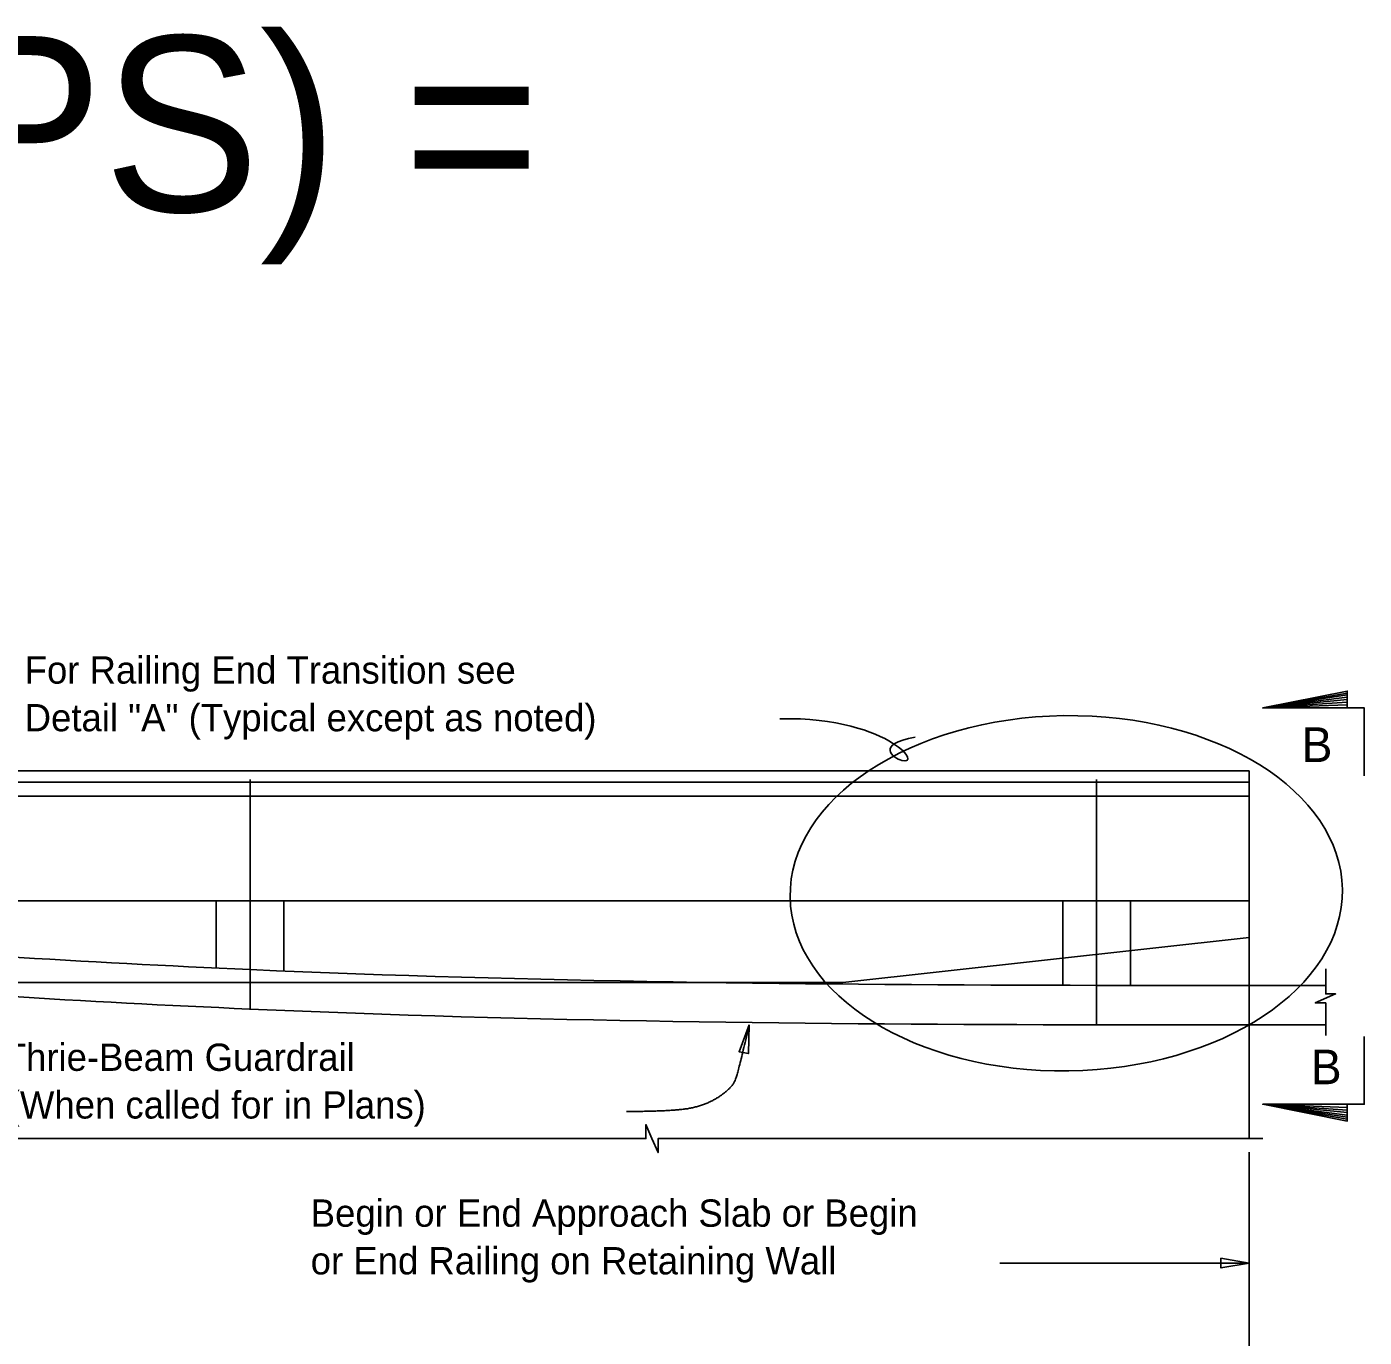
# Model space of a CAD drawing. Extents: x 130583.6 to 130653, y 88618.2 to 88652.9.
# Drawn here: x 130614.42 to 130624.29, y 88643.03 to 88652.71 of the extents above; entities that cross this region are included whole.
import ezdxf

# ---------------------------------------------------------------- set-up
doc = ezdxf.new("R2010")
doc.units = 0
for name, color, linetype in [('Dimension', 7, 'Continuous'), ('Miscellaneous', 7, 'Continuous'), ('TextStructures', 7, 'Continuous'), ('TrafBarrierConc', 7, 'Continuous')]:
    doc.layers.add(name, color=color, linetype=linetype)

msp = doc.modelspace()

# ---------------------------------------------------------------- linework, layer by layer
at = {"layer": 'Dimension'}
for p, q in [((130623.5402, 88647.6781), (130624.1652, 88647.7881)), ((130624.1652, 88647.7748), (130623.5402, 88647.6781)), ((130623.5402, 88647.6781), (130624.1652, 88647.7581)), ((130624.1652, 88647.7398), (130623.5402, 88647.6781)), ((130623.5402, 88647.6781), (130624.1652, 88647.7215)), ((130624.1652, 88647.7015), (130623.5402, 88647.6781)), ((130616.0642, 88647.1509), (130616.0642, 88645.4549)), ((130622.3142, 88647.1509), (130622.3142, 88645.3384)), ((130624.1652, 88644.7292), (130623.5402, 88644.7525)), ((130623.5402, 88644.7525), (130624.1652, 88644.7092)), ((130624.1652, 88644.6909), (130623.5402, 88644.7525)), ((130623.5402, 88644.7525), (130624.1652, 88644.6725)), ((130624.1652, 88644.6559), (130623.5402, 88644.7525)), ((130623.5402, 88644.7525), (130624.1652, 88644.6425)), ((130623.4397, 88638.1338), (130623.4397, 88644.3981)), ((130621.5998, 88643.5794), (130623.4397, 88643.5794))]:
    msp.add_line(p, q, dxfattribs=at)
for points in [[(130624.2902, 88647.1781), (130624.2902, 88647.6781), (130623.5402, 88647.6781), (130624.1652, 88647.8031), (130624.1652, 88647.6781)], [(130624.006, 88645.2589), (130624.006, 88645.5001), (130623.9285, 88645.5001), (130624.0785, 88645.5663), (130624.006, 88645.5663), (130624.006, 88645.7521)], [(130624.2902, 88645.2525), (130624.2902, 88644.7525), (130623.5402, 88644.7525), (130624.1652, 88644.6275), (130624.1652, 88644.7525)], [(130614.2317, 88644.4989), (130618.986, 88644.4989), (130618.986, 88644.6022), (130619.031, 88644.4989), (130619.076, 88644.3956), (130619.076, 88644.4989), (130623.5405, 88644.4989)]]:
    msp.add_lwpolyline(points, dxfattribs=at)
for points in [[(130619.7487, 88645.3379), (130619.6743, 88645.1402), (130619.7436, 88645.1268)], [(130623.4397, 88643.5794), (130623.2315, 88643.6147), (130623.2315, 88643.5441)]]:
    msp.add_lwpolyline(points, close=True, dxfattribs=at)
msp.add_ellipse((130622.0902, 88646.3101), major_axis=(2.0389, 0.0288), ratio=0.643163, dxfattribs=at)
for points, degree in [([(130620.9753, 88647.4629), (130620.6779, 88647.4097), (130620.9434, 88647.2079), (130620.9434, 88647.3991), (130620.3975, 88647.6078), (130619.9761, 88647.5987)], 3), ([(130618.8423, 88644.699), (130619.1151, 88644.699), (130619.4055, 88644.7313), (130619.6226, 88644.8691), (130619.6695, 88644.9924), (130619.7487, 88645.3379)], 2)]:
    msp.add_open_spline(points, degree=degree, dxfattribs=at)
at = {"layer": 'Miscellaneous'}
for p, q in [((130615.8142, 88645.7578), (130615.8142, 88646.2551)), ((130616.3142, 88645.7362), (130616.3142, 88646.2551)), ((130622.0642, 88645.6305), (130622.0642, 88646.2551)), ((130622.5642, 88645.6301), (130622.5642, 88646.2551))]:
    msp.add_line(p, q, dxfattribs=at)
for points in [[(130608.7957, 88646.2552), (130616.0642, 88645.7468), (130622.3142, 88645.6301), (130624.006, 88645.6301)], [(130608.7957, 88645.9634), (130616.0609, 88645.4551), (130622.3115, 88645.3384), (130624.006, 88645.3384)]]:
    msp.add_spline(points, degree=3, dxfattribs=at)
at = {"layer": 'TrafBarrierConc'}
for p, q in [((130607.4586, 88647.2134), (130623.4397, 88647.2134)), ((130623.4397, 88647.2134), (130623.4397, 88644.4989)), ((130607.4586, 88647.1299), (130623.4397, 88647.1299)), ((130607.4586, 88647.0257), (130623.4397, 88647.0257)), ((130607.4586, 88646.2551), (130623.4397, 88646.2551)), ((130620.4397, 88645.6509), (130623.4397, 88645.9822)), ((130607.4586, 88645.6509), (130620.4397, 88645.6509))]:
    msp.add_line(p, q, dxfattribs=at)

# ---------------------------------------------------------------- texts
at = {"layer": 'Dimension'}
for s, p in [('For Railing End Transition see ', (130614.3997, 88647.8579)), ('Detail "A" (Typical except as noted)', (130614.3997, 88647.5059))]:
    msp.add_text(s, height=0.2016, dxfattribs=at).set_placement(p)
for s, p in [('Begin or End Approach Slab or Begin ', (130616.5118, 88643.8478)), ('or End Railing on Retaining Wall', (130616.5118, 88643.4958))]:
    msp.add_text(s, height=0.2016, rotation=360, dxfattribs=at).set_placement(p)
at = {"layer": 'TextStructures'}
for s, height, p in [('Pattern Scale (PS) = ', 1.296003, (130602.3606, 88651.3429)), ('Approach Thrie-Beam Guardrail ', 0.2016, (130613.0163, 88644.9986)), ('Transition (When called for in Plans)', 0.2016, (130613.0163, 88644.6466))]:
    msp.add_text(s, height=height, dxfattribs=at).set_placement(p)
for p in [(130623.8269, 88647.2792), (130623.8949, 88644.8999)]:
    msp.add_text('B', height=0.256, rotation=360, dxfattribs=at).set_placement(p)

doc.saveas('drawing.dxf')
